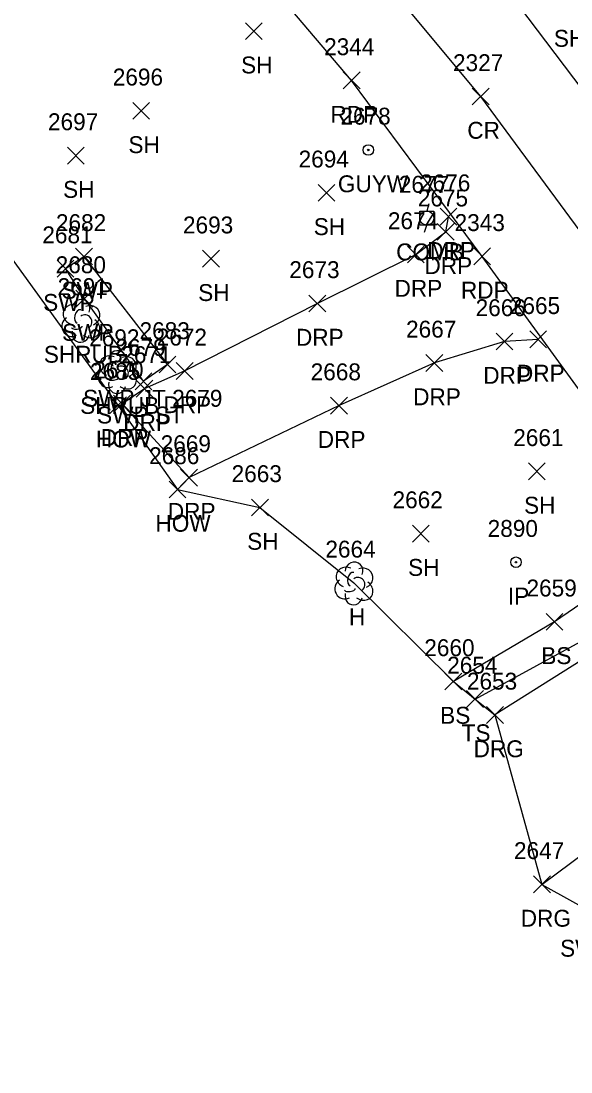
# Model space of a CAD drawing. Extents: x 1638344 to 1639591, y 610835 to 612202.
# Drawn here: x 1638879.7 to 1638944.8, y 611458.3 to 611582.6 of the extents above; entities that cross this region are included whole.
import ezdxf

# ---------------------------------------------------------------- set-up
doc = ezdxf.new("R2010")
doc.units = 0
for name, color, linetype in [('L_A', 7, 'Continuous'), ('L_I', 7, 'Continuous'), ('L_TIC', 7, 'Continuous'), ('LBC', 7, 'Continuous'), ('LELB', 7, 'Continuous'), ('LSH', 7, 'Continuous'), ('LSOGP', 7, 'Continuous'), ('LTD', 7, 'Continuous'), ('M_A', 7, 'Continuous'), ('M_I', 7, 'Continuous'), ('MPIR', 7, 'Continuous'), ('P_A', 7, 'Continuous'), ('P_I', 7, 'Continuous'), ('P_TIC', 7, 'Continuous'), ('PET', 7, 'Continuous'), ('PRC', 7, 'Continuous'), ('R_A', 7, 'Continuous'), ('R_I', 7, 'Continuous'), ('R_TIC', 7, 'Continuous'), ('RDG', 7, 'Continuous'), ('RDP', 7, 'Continuous'), ('RSW', 7, 'Continuous'), ('U_A', 7, 'Continuous'), ('U_I', 7, 'Continuous'), ('UP', 7, 'Continuous'), ('UPGW', 7, 'Continuous')]:
    doc.layers.add(name, color=color, linetype=linetype)

msp = doc.modelspace()

# ---------------------------------------------------------------- linework, layer by layer
at = {"layer": 'L_TIC'}
for points in [[(1638906.3, 611580.42), (1638908.3, 611582.41)], [(1638908.3, 611580.42), (1638906.3, 611582.41)], [(1638892.96, 611570.99), (1638894.96, 611572.99)], [(1638894.96, 611570.99), (1638892.96, 611572.99)], [(1638885.23, 611565.7), (1638887.23, 611567.7)], [(1638887.23, 611565.7), (1638885.23, 611567.7)], [(1638914.91, 611561.29), (1638916.9, 611563.29)], [(1638916.9, 611561.29), (1638914.91, 611563.29)], [(1638901.22, 611553.49), (1638903.22, 611555.49)], [(1638903.22, 611553.49), (1638901.22, 611555.49)], [(1638890.21, 611536.16), (1638892.21, 611538.16)], [(1638892.21, 611536.16), (1638890.21, 611538.16)], [(1638939.8, 611528.33), (1638941.8, 611530.33)], [(1638941.8, 611528.33), (1638939.8, 611530.33)], [(1638897.26, 611526.19), (1638899.26, 611528.19)], [(1638899.26, 611526.19), (1638897.26, 611528.19)], [(1638907.03, 611524.06), (1638909.02, 611526.06)], [(1638909.02, 611524.06), (1638907.03, 611526.06)], [(1638926.07, 611520.97), (1638928.07, 611522.97)], [(1638928.07, 611520.97), (1638926.07, 611522.97)], [(1638941.89, 611510.53), (1638943.89, 611512.53)], [(1638943.89, 611510.53), (1638941.89, 611512.53)], [(1638929.92, 611503.47), (1638931.92, 611505.47)], [(1638931.92, 611503.47), (1638929.92, 611505.47)], [(1638932.49, 611501.4), (1638934.49, 611503.4)], [(1638934.49, 611501.4), (1638932.49, 611503.4)]]:
    msp.add_lwpolyline(points, dxfattribs=at)
at = {"layer": 'LBC'}
msp.add_lwpolyline([(1638866.35, 611571.46), (1638891.21, 611537.16), (1638898.26, 611527.19)], dxfattribs=at)
at = {"layer": 'LELB'}
for points in [[(1638951.25, 611524.96), (1638953.37, 611518.66), (1638942.89, 611511.53), (1638930.92, 611504.47)], [(1638933.49, 611502.4), (1638948.09, 611510.33), (1638954.93, 611516.74)]]:
    msp.add_lwpolyline(points, dxfattribs=at)
at = {"layer": 'LSH'}
for p, q in [((1638886.81, 611547.19), (1638886.81, 611547.19)), ((1638886.81, 611547.19), (1638886.81, 611547.19)), ((1638891.11, 611541.14), (1638891.11, 611541.14)), ((1638891.11, 611541.14), (1638891.11, 611541.14))]:
    msp.add_line(p, q, dxfattribs=at)
for centre in [(1638886.85, 611548.62), (1638891.16, 611542.57)]:
    msp.add_arc(centre, 1.05, 335.5272, 180.9563, dxfattribs=at)
for centre, major_axis, ratio, start_param, end_param in [((1638886.02, 611547.86), (1.21, -0.51), 0.895232, 1.570796, 4.712389), ((1638886.6, 611547.65), (-0.208, -0.792), 0.645439, 3.141593, 6.283185), ((1638887.85, 611547.77), (-1.14, -0.48), 0.949671, 1.570796, 4.712389), ((1638885.72, 611546.48), (0.58, -1.04), 0.959034, 3.141593, 6.283185), ((1638887.31, 611547.02), (-0.5, 0.667), 0.989748, 3.141593, 6.283185), ((1638887.81, 611546.36), (-1.09, 0.79), 0.841452, 1.570796, 4.712389), ((1638886.81, 611545.69), (0.26, 1.06), 0.942809, 1.570796, 4.712389), ((1638886.35, 611546.44), (-0.625, -0.083), 0.423636, 0, 3.141593), ((1638890.32, 611541.8), (1.21, -0.51), 0.895232, 1.570796, 4.712389), ((1638890.91, 611541.59), (-0.208, -0.792), 0.645439, 3.141593, 6.283185), ((1638892.16, 611541.72), (-1.14, -0.48), 0.949671, 1.570796, 4.712389), ((1638890.03, 611540.43), (0.58, -1.04), 0.959034, 3.141593, 6.283185), ((1638891.62, 611540.97), (-0.5, 0.667), 0.989748, 3.141593, 6.283185), ((1638892.12, 611540.3), (-1.09, 0.79), 0.841452, 1.570796, 4.712389), ((1638891.12, 611539.64), (0.26, 1.06), 0.942809, 1.570796, 4.712389), ((1638890.66, 611540.39), (-0.625, -0.083), 0.423636, 0, 3.141593)]:
    msp.add_ellipse(centre, major_axis=major_axis, ratio=ratio, start_param=start_param, end_param=end_param, dxfattribs=at)
at = {"layer": 'LSOGP'}
msp.add_lwpolyline([(1638866.35, 611571.46), (1638891.21, 611537.16), (1638898.26, 611527.19), (1638908.02, 611525.06), (1638919.13, 611516.13), (1638930.92, 611504.47), (1638933.49, 611502.4), (1638935.84, 611500.51), (1638941.41, 611480.46), (1638948.31, 611476.61), (1638953.37, 611468.84), (1638958.39, 611472.15), (1638967.12, 611459.42), (1638975.07, 611447.92), (1638970.75, 611444.76), (1638975.17, 611438.04), (1638967.49, 611433.08), (1638975.65, 611412.07), (1638983.02, 611400.9), (1638992.44, 611393.68), (1638995.76, 611397.43), (1639012.69, 611385.24), (1639028.13, 611374.16)], dxfattribs=at)
at = {"layer": 'LTD'}
msp.add_line((1638919.13, 611516.13), (1638919.13, 611516.13), dxfattribs=at)
msp.add_line((1638919.13, 611516.13), (1638919.13, 611516.13), dxfattribs=at)
msp.add_arc((1638919.17, 611517.56), 1.05, 335.5272, 180.9563, dxfattribs=at)
for centre, major_axis, ratio, start_param, end_param in [((1638918.34, 611516.8), (1.21, -0.51), 0.895232, 1.570796, 4.712389), ((1638918.92, 611516.59), (-0.208, -0.792), 0.645439, 3.141593, 6.283185), ((1638920.17, 611516.71), (-1.14, -0.48), 0.949671, 1.570796, 4.712389), ((1638918.04, 611515.42), (0.58, -1.04), 0.959034, 3.141593, 6.283185), ((1638919.63, 611515.96), (-0.5, 0.667), 0.989748, 3.141593, 6.283185), ((1638920.13, 611515.3), (-1.09, 0.79), 0.841452, 1.570796, 4.712389), ((1638919.13, 611514.63), (0.26, 1.06), 0.942809, 1.570796, 4.712389), ((1638918.67, 611515.38), (-0.625, -0.083), 0.423636, 0, 3.141593)]:
    msp.add_ellipse(centre, major_axis=major_axis, ratio=ratio, start_param=start_param, end_param=end_param, dxfattribs=at)
at = {"layer": 'MPIR'}
for radius in [0.625, 0.0833]:
    msp.add_circle((1638938.33, 611518.58), radius, dxfattribs=at)
at = {"layer": 'P_TIC'}
for points in [[(1638917.88, 611574.59), (1638919.88, 611576.59)], [(1638919.88, 611574.59), (1638917.88, 611576.59)], [(1638933.14, 611572.69), (1638935.14, 611574.69)], [(1638935.14, 611572.69), (1638933.14, 611574.69)], [(1638933.33, 611553.77), (1638935.33, 611555.77)], [(1638935.33, 611553.77), (1638933.33, 611555.77)]]:
    msp.add_lwpolyline(points, dxfattribs=at)
at = {"layer": 'PET'}
for points in [[(1639148.64, 611331.08), (1639142.07, 611329.18), (1639135.7, 611328.74), (1639125.69, 611331.15), (1639119.18, 611334.88), (1639114.19, 611340.57), (1639098.76, 611361.78), (1639080.32, 611387.34), (1639061.62, 611413.48), (1639039.15, 611444.22), (1639014.34, 611480.36), (1638988.41, 611516.9), (1638963.39, 611551.85), (1638935.46, 611588.7), (1638918.51, 611609.36), (1638899.73, 611630.86), (1638874.41, 611653.86), (1638846.55, 611674.47), (1638833.14, 611682.54), (1638823.86, 611689.16)], [(1639117.36, 611283.38), (1639114.12, 611301.89), (1639095.51, 611328.5), (1639070.51, 611363.26), (1639041.38, 611404.69), (1639011.58, 611446.4), (1638984.33, 611485.15), (1638954.17, 611527.5), (1638934.33, 611554.77), (1638918.88, 611575.58), (1638893.27, 611605.67), (1638868.12, 611629.84), (1638836.66, 611652.85), (1638812.43, 611667.64)]]:
    msp.add_lwpolyline(points, dxfattribs=at)
at = {"layer": 'PRC'}
msp.add_lwpolyline([(1638818.79, 611678.84), (1638843.98, 611663.35), (1638876.44, 611637.39), (1638906.24, 611607.19), (1638934.14, 611573.69), (1638965.31, 611531.43), (1638998.82, 611484.34), (1639033.82, 611434.48), (1639068.01, 611386.3), (1639093.94, 611350.49), (1639111.89, 611325.38), (1639129.23, 611302.77)], dxfattribs=at)
at = {"layer": 'R_TIC'}
for points in [[(1638929.34, 611558.47), (1638931.34, 611560.47)], [(1638931.34, 611558.47), (1638929.34, 611560.47)], [(1638929.02, 611556.68), (1638931.02, 611558.68)], [(1638931.02, 611556.68), (1638929.02, 611558.68)], [(1638886.18, 611553.76), (1638888.18, 611555.75)], [(1638888.18, 611553.76), (1638886.18, 611555.75)], [(1638925.48, 611553.99), (1638927.48, 611555.99)], [(1638927.48, 611553.99), (1638925.48, 611555.99)], [(1638884, 611552.32), (1638886, 611554.32)], [(1638886, 611552.32), (1638884, 611554.32)], [(1638886.24, 611548.78), (1638888.24, 611550.78)], [(1638888.24, 611548.78), (1638886.24, 611550.78)], [(1638913.81, 611548.2), (1638915.81, 611550.2)], [(1638915.81, 611548.2), (1638913.81, 611550.2)], [(1638939.96, 611543.95), (1638941.96, 611545.95)], [(1638941.96, 611543.95), (1638939.96, 611545.95)], [(1638935.97, 611543.7), (1638937.97, 611545.7)], [(1638937.97, 611543.7), (1638935.97, 611545.7)], [(1638896.08, 611540.98), (1638898.08, 611542.98)], [(1638898.08, 611540.98), (1638896.08, 611542.98)], [(1638898.1, 611540.22), (1638900.1, 611542.22)], [(1638900.1, 611540.22), (1638898.1, 611542.22)], [(1638927.67, 611541.16), (1638929.67, 611543.16)], [(1638929.67, 611541.16), (1638927.67, 611543.16)], [(1638893.24, 611539), (1638895.24, 611541)], [(1638895.24, 611539), (1638893.24, 611541)], [(1638893.35, 611538.13), (1638895.35, 611540.13)], [(1638895.35, 611538.13), (1638893.35, 611540.13)], [(1638890.69, 611536.34), (1638892.69, 611538.34)], [(1638892.69, 611536.34), (1638890.69, 611538.34)], [(1638916.38, 611536.11), (1638918.38, 611538.11)], [(1638918.38, 611536.11), (1638916.38, 611538.11)], [(1638898.63, 611527.6), (1638900.63, 611529.6)], [(1638900.63, 611527.6), (1638898.63, 611529.6)], [(1638934.84, 611499.51), (1638936.84, 611501.51)], [(1638936.84, 611499.51), (1638934.84, 611501.51)], [(1638940.41, 611479.46), (1638942.41, 611481.46)], [(1638942.41, 611479.46), (1638940.41, 611481.46)]]:
    msp.add_lwpolyline(points, dxfattribs=at)
at = {"layer": 'RDG'}
msp.add_lwpolyline([(1638941.41, 611480.46), (1638956.84, 611491.94), (1638965.08, 611500.79), (1638971.28, 611501.89), (1638960.27, 611516.66), (1638954.16, 611512.04), (1638935.84, 611500.51)], dxfattribs=at)
at = {"layer": 'RDP'}
msp.add_lwpolyline([(1638940.96, 611544.95), (1638936.97, 611544.7), (1638928.67, 611542.16), (1638917.39, 611537.11), (1638899.63, 611528.6), (1638891.69, 611537.34), (1638894.35, 611539.14), (1638899.1, 611541.22), (1638914.81, 611549.2), (1638926.48, 611554.99), (1638930.02, 611557.68), (1638930.34, 611559.47)], dxfattribs=at)
at = {"layer": 'RSW'}
for points in [[(1638894.24, 611540), (1638887.24, 611549.78), (1638885, 611553.32), (1638887.18, 611554.76), (1638897.08, 611541.98)], [(1638897.08, 611541.98), (1638894.24, 611540)]]:
    msp.add_lwpolyline(points, dxfattribs=at)
at = {"layer": 'UP'}
for p, q in [((1638928.02, 611560.97), (1638927.77, 611560.14)), ((1638926.94, 611558.47), (1638926.94, 611560.14)), ((1638926.94, 611560.14), (1638928.6, 611560.14)), ((1638928.6, 611560.14), (1638928.6, 611558.47)), ((1638928.6, 611558.47), (1638926.94, 611558.47)), ((1638927.52, 611557.64), (1638927.77, 611558.47)), ((1638927.77, 611559.3), (1638927.77, 611559.3))]:
    msp.add_line(p, q, dxfattribs=at)
msp.add_circle((1638927.77, 611559.3), 0.833, dxfattribs=at)
at = {"layer": 'UPGW'}
for radius in [0.625, 0.0833]:
    msp.add_circle((1638920.85, 611567.36), radius, dxfattribs=at)

# ---------------------------------------------------------------- texts
at = {"layer": 'L_A'}
for s, p in [('SH', (1638942.82, 611579.57)), ('SH', (1638905.79, 611576.42)), ('SH', (1638892.45, 611566.99)), ('SH', (1638884.72, 611561.7)), ('SH', (1638914.39, 611557.29)), ('SH', (1638900.71, 611549.49)), ('SHRUB', (1638882.44, 611542.19)), ('SHRUB', (1638886.74, 611536.14)), ('HOW', (1638888.6, 611532.16)), ('SH', (1638939.29, 611524.33)), ('HOW', (1638895.65, 611522.19)), ('SH', (1638906.51, 611520.06)), ('SH', (1638925.56, 611516.97)), ('H', (1638918.56, 611511.13)), ('BS', (1638941.33, 611506.53)), ('BS', (1638929.36, 611499.47)), ('TS', (1638931.9, 611497.4))]:
    msp.add_text(s, height=2, dxfattribs=at).set_placement(p)
at = {"layer": 'L_I'}
for s, p in [('2696', (1638890.6, 611574.99)), ('2697', (1638882.93, 611569.7)), ('2694', (1638912.6, 611565.29)), ('2693', (1638898.91, 611557.49)), ('2691', (1638884.07, 611550.19)), ('2692', (1638887.81, 611544.14)), ('2685', (1638887.9, 611540.16)), ('2661', (1638938.01, 611532.33)), ('2686', (1638894.9, 611530.19)), ('2663', (1638904.67, 611528.06)), ('2662', (1638923.72, 611524.97)), ('2664', (1638915.77, 611519.13)), ('2659', (1638939.58, 611514.53)), ('2660', (1638927.48, 611507.47)), ('2654', (1638930.19, 611505.4))]:
    msp.add_text(s, height=2, dxfattribs=at).set_placement(p)
at = {"layer": 'M_A'}
msp.add_text('IP', height=2, dxfattribs=at).set_placement((1638937.38, 611513.58))
at = {"layer": 'M_I'}
msp.add_text('2890', height=2, dxfattribs=at).set_placement((1638934.98, 611521.58))
at = {"layer": 'P_A'}
for s, p in [('RDP', (1638916.37, 611570.58)), ('CR', (1638932.57, 611568.69)), ('RDP', (1638931.82, 611549.77))]:
    msp.add_text(s, height=2, dxfattribs=at).set_placement(p)
at = {"layer": 'P_I'}
for s, p in [('2344', (1638915.62, 611578.58)), ('2327', (1638930.88, 611576.69)), ('2343', (1638931.07, 611557.77))]:
    msp.add_text(s, height=2, dxfattribs=at).set_placement(p)
at = {"layer": 'R_A'}
for s, p in [('DRP', (1638927.83, 611554.47)), ('DRP', (1638927.5, 611552.68)), ('DRP', (1638923.96, 611549.99)), ('SWP', (1638884.54, 611549.75)), ('SWP', (1638882.36, 611548.32)), ('SWP', (1638884.6, 611544.78)), ('DRP', (1638912.29, 611544.2)), ('DRP', (1638934.46, 611539.7)), ('DRP', (1638938.45, 611539.95)), ('SWP JT 2679', (1638887.08, 611536.98)), ('DRP', (1638926.16, 611537.16)), ('SWP ST', (1638888.74, 611535)), ('DRP', (1638896.59, 611536.22)), ('DRP', (1638891.84, 611534.13)), ('DRP', (1638889.17, 611532.34)), ('DRP', (1638914.87, 611532.11)), ('DRP', (1638897.12, 611523.6)), ('DRG', (1638933.32, 611495.51)), ('DRG', (1638938.9, 611475.46)), ('SWP ST', (1638943.56, 611471.91))]:
    msp.add_text(s, height=2, dxfattribs=at).set_placement(p)
at = {"layer": 'R_I'}
for s, p in [('2676', (1638926.98, 611562.47)), ('2675', (1638926.71, 611560.68)), ('2682', (1638883.87, 611557.76)), ('2674', (1638923.17, 611557.99)), ('2681', (1638882.26, 611556.32)), ('2680', (1638883.84, 611552.78)), ('2673', (1638911.5, 611552.2)), ('2666', (1638933.56, 611547.7)), ('2665', (1638937.61, 611547.95)), ('2683', (1638893.77, 611544.98)), ('2667', (1638925.32, 611545.16)), ('2672', (1638895.8, 611544.22)), ('2679', (1638890.92, 611543)), ('2671', (1638891.61, 611542.14)), ('2670', (1638888.29, 611540.34)), ('2668', (1638914.03, 611540.11)), ('2669', (1638896.27, 611531.6)), ('2653', (1638932.53, 611503.51)), ('2647', (1638938.1, 611483.46))]:
    msp.add_text(s, height=2, dxfattribs=at).set_placement(p)
at = {"layer": 'U_A'}
for s, p in [('GUYW', (1638917.25, 611562.36)), ('COMB', (1638924.15, 611554.3))]:
    msp.add_text(s, height=2, dxfattribs=at).set_placement(p)
at = {"layer": 'U_I'}
for s, p in [('2678', (1638917.55, 611570.36)), ('2677', (1638924.46, 611562.3))]:
    msp.add_text(s, height=2, dxfattribs=at).set_placement(p)

doc.saveas('drawing.dxf')
